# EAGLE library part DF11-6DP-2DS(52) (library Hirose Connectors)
CONN, VERT, PTH, 6P, 3x2, 2 MM PITCH, RT ANGLE, GOLD (HIROSE)
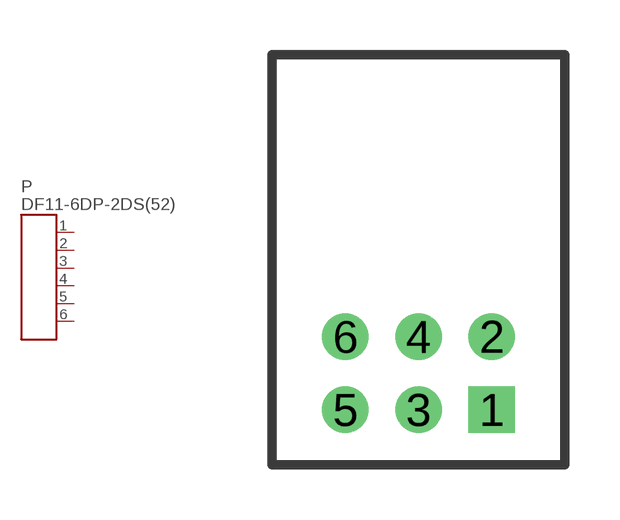
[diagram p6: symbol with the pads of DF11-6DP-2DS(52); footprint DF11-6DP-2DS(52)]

Designator prefix P

## DF11-6DP-2DS(52)  [DF11-6DP-2DS(52)]
1  P$1
2  P$2
3  P$3
4  P$4
5  P$5
6  P$6

## Footprint DF11-6DP-2DS(52) (pad centres in mm)
drill 0.737 pad 1.27 square: 1 2,-1
drill 0.737 pad 1.27 round: 2 2,1; 3 0,-1; 4 0,1; 5 -2,-1; 6 -2,1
